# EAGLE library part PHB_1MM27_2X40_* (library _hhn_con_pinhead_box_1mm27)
Pin Header Box-Type, 1.27mm/0.5"/50mil Pitch, 2x40 Circuits Note: see library description for an important note about THT-version
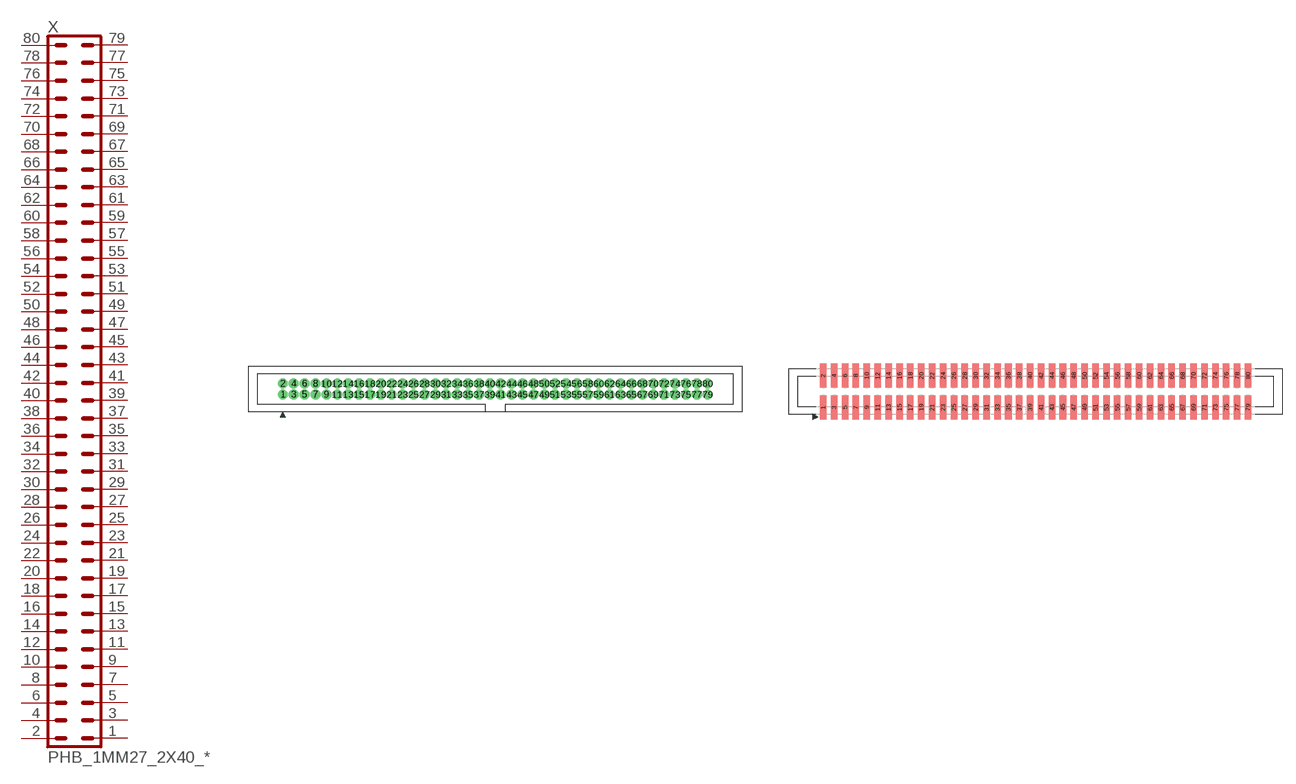
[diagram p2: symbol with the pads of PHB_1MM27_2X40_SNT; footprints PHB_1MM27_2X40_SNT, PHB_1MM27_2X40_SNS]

Designator prefix X

## PHB_1MM27_2X40_SNT  [PHB_1MM27_2X40_SNT]
1  1  pas
2  2  pas
3  3  pas
4  4  pas
5  5  pas
6  6  pas
7  7  pas
8  8  pas
9  9  pas
10  10  pas
11  11  pas
12  12  pas
13  13  pas
14  14  pas
15  15  pas
16  16  pas
17  17  pas
18  18  pas
19  19  pas
20  20  pas
21  21  pas
22  22  pas
23  23  pas
24  24  pas
25  25  pas
26  26  pas
27  27  pas
28  28  pas
29  29  pas
30  30  pas
31  31  pas
32  32  pas
33  33  pas
34  34  pas
35  35  pas
36  36  pas
37  37  pas
38  38  pas
39  39  pas
40  40  pas
41  41  pas
42  42  pas
43  43  pas
44  44  pas
45  45  pas
46  46  pas
47  47  pas
48  48  pas
49  49  pas
50  50  pas
51  51  pas
52  52  pas
53  53  pas
54  54  pas
55  55  pas
56  56  pas
57  57  pas
58  58  pas
59  59  pas
60  60  pas
61  61  pas
62  62  pas
63  63  pas
64  64  pas
65  65  pas
66  66  pas
67  67  pas
68  68  pas
69  69  pas
70  70  pas
71  71  pas
72  72  pas
73  73  pas
74  74  pas
75  75  pas
76  76  pas
77  77  pas
78  78  pas
79  79  pas
80  80  pas

## PHB_1MM27_2X40_SNS  [PHB_1MM27_2X40_SNS]
Pads as for PHB_1MM27_2X40_SNT

## Footprint PHB_1MM27_2X40_SNT (pad centres in mm)
Pin Header Box-Type, 1.27mm Pitch, 2x40 circuits, Straight, No Locking, THT Important Note: Diameter in this lbr is set to a specific value (NOT 'auto' = 0), this is ignored by actual eagle versions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
drill 0.65 pad 1 round: 1 -24.765,-0.635; 2 -24.765,0.635; 3 -23.495,-0.635; 4 -23.495,0.635; 5 -22.225,-0.635; 6 -22.225,0.635; 7 -20.955,-0.635; 8 -20.955,0.635; 9 -19.685,-0.635; 10 -19.685,0.635; 11 -18.415,-0.635; 12 -18.415,0.635; 13 -17.145,-0.635; 14 -17.145,0.635; 15 -15.875,-0.635; 16 -15.875,0.635; 17 -14.605,-0.635; 18 -14.605,0.635; 19 -13.335,-0.635; 20 -13.335,0.635; 21 -12.065,-0.635; 22 -12.065,0.635; 23 -10.795,-0.635; 24 -10.795,0.635; 25 -9.525,-0.635; 26 -9.525,0.635; 27 -8.255,-0.635; 28 -8.255,0.635; 29 -6.985,-0.635; 30 -6.985,0.635; 31 -5.715,-0.635; 32 -5.715,0.635; 33 -4.445,-0.635; 34 -4.445,0.635; 35 -3.175,-0.635; 36 -3.175,0.635; 37 -1.905,-0.635; 38 -1.905,0.635; 39 -0.635,-0.635; 40 -0.635,0.635; 41 0.635,-0.635; 42 0.635,0.635; 43 1.905,-0.635; 44 1.905,0.635; 45 3.175,-0.635; 46 3.175,0.635; 47 4.445,-0.635; 48 4.445,0.635; 49 5.715,-0.635; 50 5.715,0.635; 51 6.985,-0.635; 52 6.985,0.635; 53 8.255,-0.635; 54 8.255,0.635; 55 9.525,-0.635; 56 9.525,0.635; 57 10.795,-0.635; 58 10.795,0.635; 59 12.065,-0.635; 60 12.065,0.635; 61 13.335,-0.635; 62 13.335,0.635; 63 14.605,-0.635; 64 14.605,0.635; 65 15.875,-0.635; 66 15.875,0.635; 67 17.145,-0.635; 68 17.145,0.635; 69 18.415,-0.635; 70 18.415,0.635; 71 19.685,-0.635; 72 19.685,0.635; 73 20.955,-0.635; 74 20.955,0.635; 75 22.225,-0.635; 76 22.225,0.635; 77 23.495,-0.635; 78 23.495,0.635; 79 24.765,-0.635; 80 24.765,0.635

## Footprint PHB_1MM27_2X40_SNS (pad centres in mm)
Pin Header Box-Type, 1.27mm Pitch, 2x40 circuits, Straight, No Locking, SMT
smd 0.76 x 2.8: 1 -24.765,-1.85; 2 -24.765,1.85; 3 -23.495,-1.85; 4 -23.495,1.85; 5 -22.225,-1.85; 6 -22.225,1.85; 7 -20.955,-1.85; 8 -20.955,1.85; 9 -19.685,-1.85; 10 -19.685,1.85; 11 -18.415,-1.85; 12 -18.415,1.85; 13 -17.145,-1.85; 14 -17.145,1.85; 15 -15.875,-1.85; 16 -15.875,1.85; 17 -14.605,-1.85; 18 -14.605,1.85; 19 -13.335,-1.85; 20 -13.335,1.85; 21 -12.065,-1.85; 22 -12.065,1.85; 23 -10.795,-1.85; 24 -10.795,1.85; 25 -9.525,-1.85; 26 -9.525,1.85; 27 -8.255,-1.85; 28 -8.255,1.85; 29 -6.985,-1.85; 30 -6.985,1.85; 31 -5.715,-1.85; 32 -5.715,1.85; 33 -4.445,-1.85; 34 -4.445,1.85; 35 -3.175,-1.85; 36 -3.175,1.85; 37 -1.905,-1.85; 38 -1.905,1.85; 39 -0.635,-1.85; 40 -0.635,1.85; 41 0.635,-1.85; 42 0.635,1.85; 43 1.905,-1.85; 44 1.905,1.85; 45 3.175,-1.85; 46 3.175,1.85; 47 4.445,-1.85; 48 4.445,1.85; 49 5.715,-1.85; 50 5.715,1.85; 51 6.985,-1.85; 52 6.985,1.85; 53 8.255,-1.85; 54 8.255,1.85; 55 9.525,-1.85; 56 9.525,1.85; 57 10.795,-1.85; 58 10.795,1.85; 59 12.065,-1.85; 60 12.065,1.85; 61 13.335,-1.85; 62 13.335,1.85; 63 14.605,-1.85; 64 14.605,1.85; 65 15.875,-1.85; 66 15.875,1.85; 67 17.145,-1.85; 68 17.145,1.85; 69 18.415,-1.85; 70 18.415,1.85; 71 19.685,-1.85; 72 19.685,1.85; 73 20.955,-1.85; 74 20.955,1.85; 75 22.225,-1.85; 76 22.225,1.85; 77 23.495,-1.85; 78 23.495,1.85; 79 24.765,-1.85; 80 24.765,1.85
